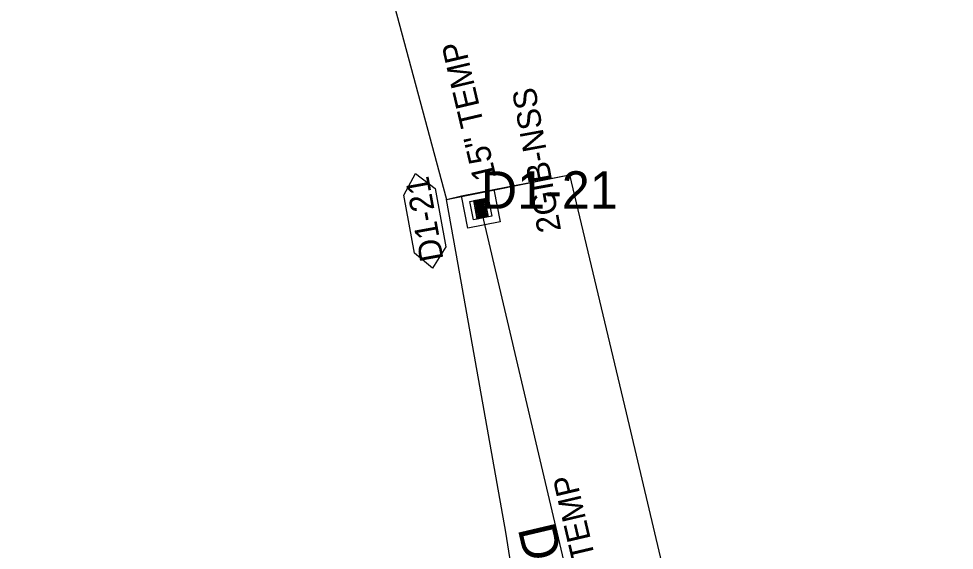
# Model space of a CAD drawing. Extents: x 465700 to 483515, y 488970 to 507540.
# Drawn here: x 481209.8 to 481409.1, y 491843.1 to 491956.4 of the extents above; entities that cross this region are included whole.
import ezdxf

# ---------------------------------------------------------------- set-up
doc = ezdxf.new("R2010")
doc.units = 0
for name, color, linetype in [('Exist Plan Preparation Watershed Blue', 7, 'Continuous'), ('Prop Drainage Structure Box Number Symbol CELL', 7, 'Continuous'), ('Prop Drainage Structure Drop Inlet Grate 2 Narrow Slots and Sag Grates 840 24 CELL', 7, 'Continuous'), ('Prop Drainage Structure Junction Box with Manhole Label', 7, 'Continuous'), ('Prop Drainage Structure Pipe RCP 15in Class III', 7, 'Continuous'), ('Prop Drainage Structure Pipe RCP 15in Class III Label', 7, 'Continuous'), ('Prop Drainage Structure Plot Symbol 20 Scale CELL', 7, 'Continuous'), ('Prop Drainage Structure Plot Symbol 50 Scale CELL', 7, 'Continuous'), ('Scratch_Level_8', 7, 'Continuous')]:
    doc.layers.add(name, color=color, linetype=linetype)

msp = doc.modelspace()

# ---------------------------------------------------------------- linework, layer by layer
at = {"layer": 'Exist Plan Preparation Watershed Blue'}
msp.add_lwpolyline([(481914.1, 492508.16), (481856.26, 492637.66), (481730.25, 492750.66), (481730.25, 492750.66), (481669.43, 492692.33), (481584.65, 492614.4), (481584.65, 492614.4), (481584.65, 492614.4), (481329.7, 492355.65), (481209.8, 492230.86), (481241.6, 492138.31), (481300.91, 491917.87), (481327.1, 491923.15), (481339.19, 491872.39), (481355.48, 491803.22), (481355.48, 491803.22), (481355.48, 491803.22)], dxfattribs=at)
msp.add_lwpolyline([(481328.95, 491769.45), (481325.82, 491768.95), (481313.54, 491846.95), (481303.37, 491904.07), (481300.91, 491917.87), (481304.12, 491918.69), (481311, 491920.02), (481327.1, 491923.15), (481339.19, 491872.39), (481355.48, 491803.22), (481358.32, 491790.73), (481338.28, 491786.26), (481331.36, 491785.24)], close=True, dxfattribs=at)
at = {"layer": 'Prop Drainage Structure Box Number Symbol CELL'}
msp.add_lwpolyline([(481294.07, 491906.44), (481291.82, 491918.84), (481294.27, 491923.46), (481298.5, 491920.22), (481300.75, 491907.82), (481297.94, 491903.24), (481294.07, 491906.44)], dxfattribs=at)
at = {"layer": 'Prop Drainage Structure Drop Inlet Grate 2 Narrow Slots and Sag Grates 840 24 CELL'}
for p, q in [((481307.85, 491917.88), (481307.85, 491917.88)), ((481307.08, 491915.7), (481307.08, 491915.7)), ((481308.23, 491915.92), (481308.23, 491915.92)), ((481309.37, 491916.14), (481309.37, 491916.14)), ((481308.61, 491913.96), (481308.61, 491913.96))]:
    msp.add_line(p, q, dxfattribs=at)
for points in [[(481308.99, 491918.11), (481309.75, 491914.18), (481307.46, 491913.73), (481306.7, 491917.66), (481308.99, 491918.11)], [(481308.94, 491918.03), (481309.68, 491914.23), (481307.51, 491913.81), (481306.77, 491917.61), (481308.94, 491918.03)], [(481308.93, 491918.02), (481309.3, 491916.14), (481307.15, 491915.72), (481306.79, 491917.6), (481308.93, 491918.02)], [(481308.79, 491917.82), (481308.82, 491917.65), (481307.03, 491917.3), (481307, 491917.48), (481308.79, 491917.82)], [(481308.84, 491917.53), (481308.88, 491917.36), (481307.09, 491917.01), (481307.05, 491917.18), (481308.84, 491917.53)], [(481308.9, 491917.24), (481308.93, 491917.07), (481307.14, 491916.72), (481307.11, 491916.89), (481308.9, 491917.24)], [(481309.3, 491916.12), (481309.67, 491914.24), (481307.52, 491913.82), (481307.16, 491915.7), (481309.3, 491916.12)], [(481308.96, 491916.95), (481308.99, 491916.77), (481307.2, 491916.43), (481307.17, 491916.6), (481308.96, 491916.95)], [(481309.01, 491916.66), (481309.05, 491916.48), (481307.26, 491916.14), (481307.22, 491916.31), (481309.01, 491916.66)], [(481309.07, 491916.37), (481309.1, 491916.19), (481307.31, 491915.84), (481307.28, 491916.02), (481309.07, 491916.37)], [(481309.14, 491916), (481309.18, 491915.82), (481307.39, 491915.48), (481307.35, 491915.65), (481309.14, 491916)], [(481309.2, 491915.71), (481309.23, 491915.53), (481307.44, 491915.18), (481307.41, 491915.36), (481309.2, 491915.71)], [(481309.25, 491915.41), (481309.29, 491915.24), (481307.5, 491914.89), (481307.47, 491915.07), (481309.25, 491915.41)], [(481309.31, 491915.12), (481309.35, 491914.95), (481307.56, 491914.6), (481307.52, 491914.78), (481309.31, 491915.12)], [(481309.37, 491914.83), (481309.4, 491914.66), (481307.61, 491914.31), (481307.58, 491914.48), (481309.37, 491914.83)], [(481309.42, 491914.54), (481309.46, 491914.37), (481307.67, 491914.02), (481307.64, 491914.19), (481309.42, 491914.54)]]:
    msp.add_lwpolyline(points, dxfattribs=at)
at = {"layer": 'Prop Drainage Structure Pipe RCP 15in Class III'}
msp.add_line((481308.23, 491915.92), (481339.42, 491783.23), dxfattribs=at)
at = {"layer": 'Prop Drainage Structure Plot Symbol 20 Scale CELL'}
msp.add_lwpolyline([(481309.81, 491918.27), (481310.57, 491914.34), (481306.65, 491913.58), (481305.88, 491917.5)], close=True, dxfattribs=at)
at = {"layer": 'Prop Drainage Structure Plot Symbol 50 Scale CELL'}
msp.add_lwpolyline([(481311, 491920.02), (481312.33, 491913.15), (481305.46, 491911.82), (481304.12, 491918.69)], close=True, dxfattribs=at)
at = {"layer": 'Scratch_Level_8'}
msp.add_line((481308.23, 491915.92), (481339.42, 491783.23), dxfattribs=at)

# ---------------------------------------------------------------- texts
at = {"layer": 'Prop Drainage Structure Box Number Symbol CELL'}
msp.add_text('D1-21', height=5, rotation=100.2925, dxfattribs=at).set_placement((481300.29, 491905.18))
at = {"layer": 'Prop Drainage Structure Junction Box with Manhole Label'}
msp.add_text('2GIB-NSS', height=5, rotation=100.2896, dxfattribs=at).set_placement((481325.34, 491911.34))
at = {"layer": 'Prop Drainage Structure Pipe RCP 15in Class III Label'}
for p in [(481311.58, 491922.54), (481335.27, 491830.17)]:
    msp.add_text('15" TEMP', height=5, rotation=103.2285, dxfattribs=at).set_placement(p)
at = {"layer": 'Scratch_Level_8'}
msp.add_text('D1-21', height=8, dxfattribs=at).set_placement((481308.23, 491915.92))
msp.add_text('D1-21', height=8, rotation=283.2285, dxfattribs=at).set_placement((481316.04, 491847.75))

doc.saveas('drawing.dxf')
